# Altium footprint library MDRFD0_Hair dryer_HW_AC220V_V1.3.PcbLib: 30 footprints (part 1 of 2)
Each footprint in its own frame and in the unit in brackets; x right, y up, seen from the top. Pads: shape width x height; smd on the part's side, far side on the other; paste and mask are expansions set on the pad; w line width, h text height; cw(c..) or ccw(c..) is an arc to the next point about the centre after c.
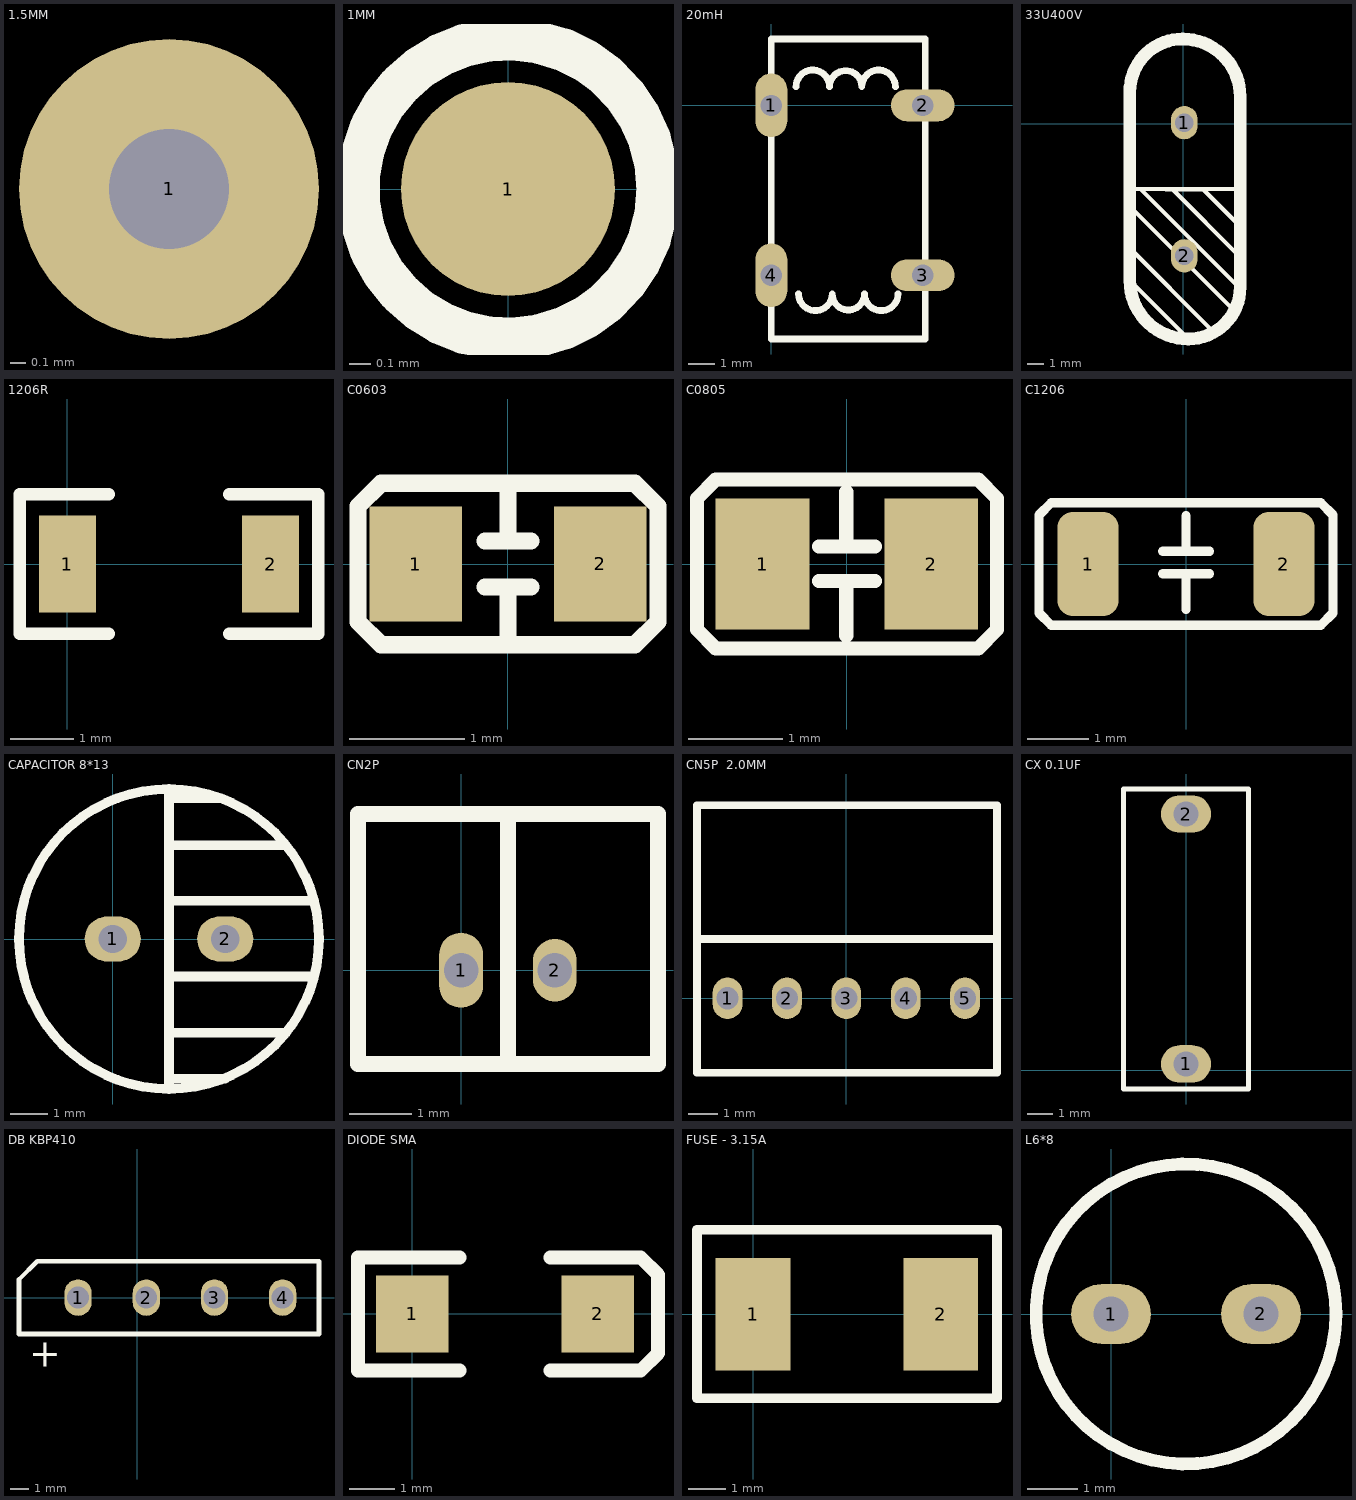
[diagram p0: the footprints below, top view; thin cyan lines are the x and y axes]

## 1.5MM [mm]
height 1.6
pads (1):
  round 2 hole 0.8: 1(2.32,-12.37)

## 1MM [mm]
height 1.6
pads (1):
  round 1 smd paste-1: 1(0,0)
Top Overlay:
  circle w0.2: c0,0 r0.7

## 20mH [mm]
pads (4):
  oval 1.2x2.4 hole 0.8: 1(0,0) 4(0,-6.4)
  oval 2.4x1.2 hole 0.8: 2(5.7,0) 3(5.7,-6.4)
Top Overlay:
  lines w0.254: 0.927,0.7 cw(c1.559,0.7) 2.192,0.7 cw(c2.8,0.7) 3.408,0.7 cw(c4.041,0.7) 4.673,0.7 ; 1.027,-7.1 ccw(c1.659,-7.1) 2.292,-7.1 ; 2.292,-7.1 ccw(c2.9,-7.1) 3.508,-7.1 ccw(c4.141,-7.1) 4.773,-7.1 ; 0,-8.8 5.8,-8.8 5.8,2.5 0,2.5 0,-8.8

## 33U400V [mm]
pads (2):
  oval 1.6x2 hole 1.1: 1(0.076,0.076) 2(0.076,-7.924)
Top Overlay:
  lines w0.254: -3.2,-9.41 0.293,-12.903 ; -3.2,-7.468 1.676,-12.344 ; -2.946,-5.207 3.175,-11.328 ; -2.54,-3.937 3.333,-9.81 ; -0.635,-3.924 3.429,-7.988 ; 3.417,-6.147 1.194,-3.924 ; 0.076,-3.924 3.429,-3.912 1.194,-3.924 ; 0.076,-3.924 -3.2,-3.912 -1.041,-3.924 0.076,-3.924 ; 0.076,-3.924 1.194,-3.924
  lines w0.762: -3.2,-9.41 ccw(c0.314,-9.41) 0.314,-12.925 ccw(c0.314,-9.81) 3.429,-9.81 3.429,1.651 ccw(c-0.025,1.651) -0.025,5.105 ccw(c-0.025,1.93) -3.2,1.93 -3.2,-9.41
Bottom Overlay:

## 1206R [mm]
pads (2):
  rect 0.9x1.524 smd: 1(0,0) 2(3.2,0)
Top Overlay:
  lines w0.2: 0.65,-1.1 -0.75,-1.1 -0.75,1.1 0.65,1.1 ; 2.55,-1.1 3.95,-1.1 3.95,1.1 2.55,1.1
3D body: height 0.55, standoff 0, extent -0.076,-0.8 3.124,0.8

## C0603 [mm]
height 15.4
pads (2):
  rect 0.8x1 smd: 1(-0.8,0) 2(0.8,0)
Top Overlay:
  lines w0.15: -0.2,-0.2 0.2,-0.2 ; -0.2,0.2 0.2,0.2 ; 0,-0.7 0,-0.2 ; 0,0.2 0,0.7 ; -1.3,-0.5 -1.1,-0.7 1.1,-0.7 1.3,-0.5 1.3,0.5 1.1,0.7 -1.1,0.7 -1.3,0.5 -1.3,-0.5
3D body: height 0.7, standoff -0.1, extent -0.8,-0.45 0.8,0.45

## C0805 [mm]
pads (2):
  rect 1x1.4 smd: 1(-0.9,0) 2(0.9,0)
Top Overlay:
  lines w0.15: -0.3,-0.18 0.3,-0.18 ; -0.3,0.188 0.3,0.188 ; -0.008,-0.761 -0.008,-0.18 ; -0.008,0.188 -0.008,0.769 ; -1.6,-0.7 -1.4,-0.9 1.4,-0.9 1.6,-0.7 1.6,0.7 1.4,0.9 -1.4,0.9 -1.6,0.7 -1.6,-0.7
3D body: height 1, standoff 0, extent -1,-0.6 1,0.65

## C1206 [mm]
pads (2):
  rrect50% 1x1.7 smd: 1(-1.6,0) 2(1.6,0)
Top Overlay:
  lines w0.15: -0.379,-0.16 0.383,-0.16 ; -0.379,0.208 0.383,0.208 ; 0.002,-0.741 0.002,-0.16 ; 0.002,0.208 0.002,0.789 ; -2.4,-0.8 -2.4,0.8 -2.2,1 2.2,1 2.4,0.8 2.4,-0.8 2.2,-1 -2.2,-1 -2.4,-0.8
3D body: height 1, standoff 0, extent -1.62,-0.8 1.58,0.8

## CAPACITOR 8*13 [mm] "¹q®e,¶¡¶Z2.5mm,ª½®"
pads (2):
  oval 1.5x1.2 hole 0.75: 1(0,0) 2(3,0)
Top Overlay:
  circle w0.254: c1.5,0 r4
  lines w0.254: 1.5,-4 1.5,4 ; 1.5,-3.725 3,-3.725 ; 1.5,-2.5 4.625,-2.5 ; 1.5,-1 5.35,-1 ; 1.5,1.025 5.375,1.025 ; 1.5,2.5 4.6,2.5 ; 1.5,3.75 2.825,3.75

## CN2P [mm]
pads (2):
  oval 0.7x1.2 hole 0.55: 1(0,0)
  oval 0.7x1 hole 0.55: 2(1.5,0)
Top Overlay:
  lines w0.254: 0.75,-1.5 0.75,2.45 ; -1.65,-1.5 -1.65,2.5 3.15,2.5 3.15,-1.5 -1.65,-1.5
Bottom Overlay:
  lines w0.5: 0.75,-0.37 0.75,0.48

## CN5P  2.0MM [mm]
pads (5):
  oval 1x1.4 hole 0.75: 1(-4,0) 2(-2,0) 3(0,0) 4(2,0) 5(4,0)
Top Overlay:
  lines w0.254: -5.03,2 5.075,2 ; -5.03,-2.5 5.075,-2.5 5.075,3 5.075,6.5 -5,6.5 -5.03,6.5 -5.03,3 -5.03,-2.5

## CX 0.1UF [mm] "¹q®e,¶¡¶Z15mm¼e9mmªø18.2mm"
pads (2):
  oval 2x1.5 hole 1: 1(0,0.25) 2(0,10.25)
Top Overlay:
  lines w0.2: -2.5,-0.75 2.5,-0.75 2.5,1.25 2.5,8.75 2.5,11.25 -2.5,11.25 -2.5,8.75 -2.5,1.25 -2.5,-0.75

## DB KBP410 [mm]
pads (4):
  oval 1.5x2 hole 1.2: 1(-3.25,0) 2(0.5,0) 3(4.25,0) 4(8,0)
Top Overlay:
  lines w0.254: -6.5,-2 -6.5,0.995 -5.5,1.995 10,1.995 10,-2 -6.5,-2
  text "+" at -5.95,-3.8 h1.52

## DIODE SMA [mm]
pads (2):
  rect 1.6x1.7 smd: 1(0,0) 2(4.1,0)
Top Overlay:
  lines w0.305: 1.05,-1.25 -1.2,-1.25 -1.2,1.25 1.05,1.25 ; 3.05,-1.25 5.05,-1.25 5.431,-0.869 5.431,0.869 5.05,1.25 3.05,1.25
3D body: height 2.15, standoff -0.05, extent -0.468,-1.35 4.532,1.35

## FUSE - 3.15A [mm] "港柬,SET-T3.15A,250V,3.15A,8.5mm*4mm*8.5mm,Pitch:5.08mm,DIP,SET Slow Blow Fuse"
pads (2):
  rect 2x3 smd: 1(0,0) 2(5,0)
Top Overlay:
  lines w0.254: -1.5,-2.245 6.5,-2.245 6.5,2.25 -1.5,2.25 -1.5,-2.245

## L6*8 [mm] "MAG.LAYERS,MCD-0608S-102MU-F-EV,1mH,0.25A,£r8mm*10mm,DIP"
pads (2):
  oval 1.6x1.2 hole 0.7: 1(0,0) 2(3,0)
Top Overlay:
  circle w0.254: c1.5,0 r3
